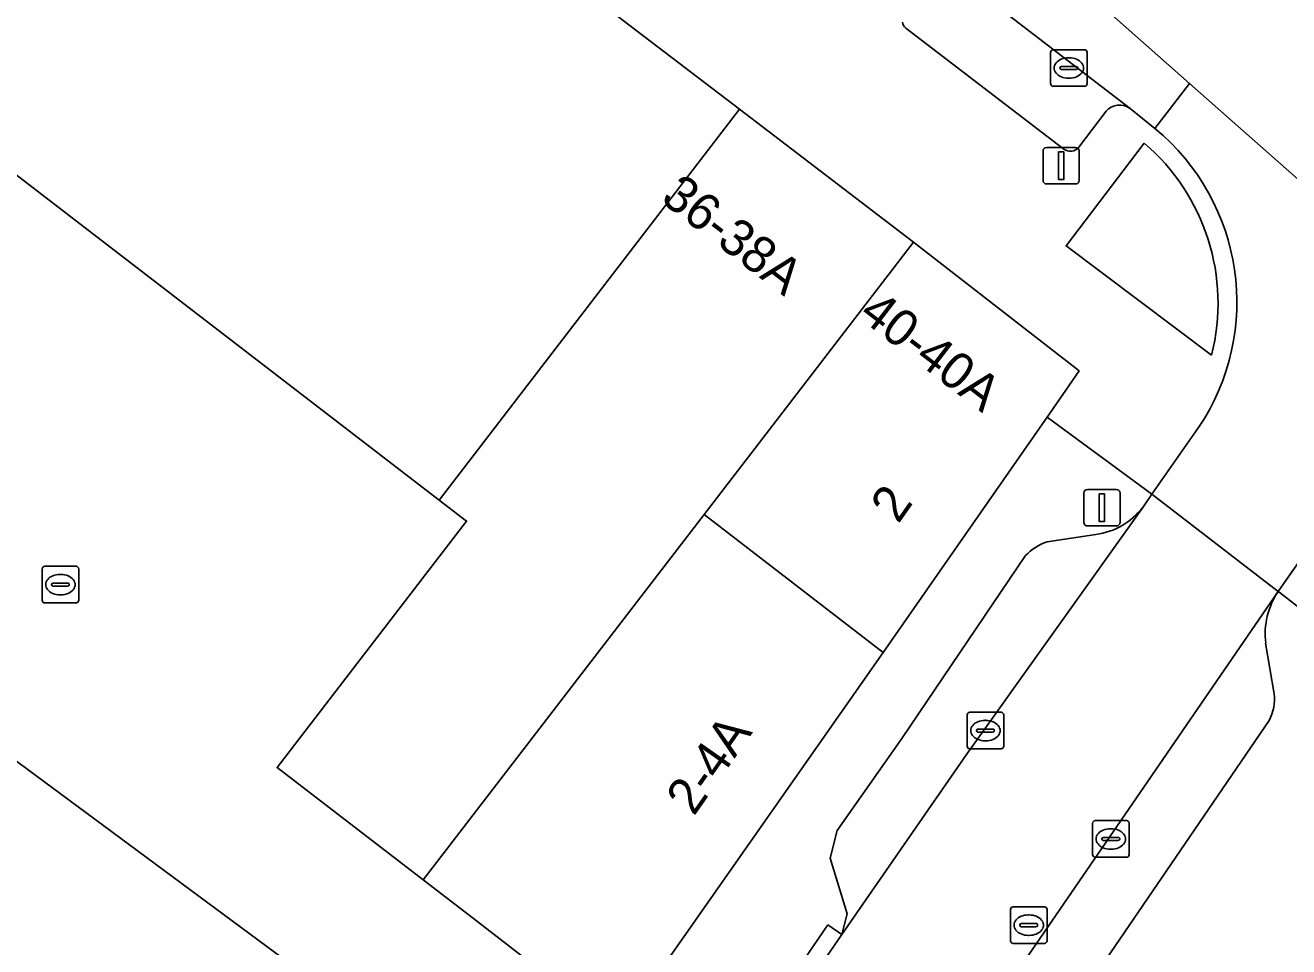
# Model space of a CAD drawing. Extents: x 161798 to 162385, y 382315 to 382833.
# Drawn here: x 161957.55 to 161992.07, y 382759.31 to 382784.49 of the extents above; entities that cross this region are included whole.
import ezdxf

# ---------------------------------------------------------------- set-up
doc = ezdxf.new("R2010")
doc.units = 0
for name, color, linetype in [('IMGEO_Groenvoorziening', 7, 'Continuous'), ('IMGEO_Kolk', 7, 'Continuous'), ('IMGEO_Lichtmast', 7, 'Continuous'), ('IMGEO_Pand', 7, 'Continuous'), ('IMGEO_Pand_nummerreeks', 7, 'Continuous'), ('IMGEO_Parkeervlak_open', 7, 'Continuous'), ('IMGEO_Rijbaan_lokaal_gesloten', 7, 'Continuous'), ('IMGEO_Rijbaan_lokaal_open', 7, 'Continuous'), ('IMGEO_Rioolput', 7, 'Continuous'), ('IMGEO_Voetpad_open', 7, 'Continuous')]:
    doc.layers.add(name, color=color, linetype=linetype)

msp = doc.modelspace()

# ---------------------------------------------------------------- linework, layer by layer
at = {"layer": 'IMGEO_Groenvoorziening'}
msp.add_lwpolyline([(161988.128, 382781.269), (161985.99, 382778.458), (161989.966, 382775.475)], dxfattribs=at)
msp.add_arc((161984.376, 382776.89), 5.766, 345.7922, 49.4085, dxfattribs=at)
at = {"layer": 'IMGEO_Kolk'}
for p, q in [((161985.64, 382783.82), (161986.492, 382783.82)), ((161985.565, 382782.894), (161985.565, 382783.746)), ((161986.053, 382783.6), (161986.078, 382783.6)), ((161986.566, 382783.746), (161986.566, 382782.894)), ((161985.824, 382783.314), (161985.824, 382783.326)), ((161986.262, 382783.277), (161985.864, 382783.277)), ((161985.867, 382783.363), (161986.265, 382783.363)), ((161986.308, 382783.326), (161986.308, 382783.314)), ((161986.492, 382782.82), (161985.64, 382782.82)), ((161986.076, 382783.04), (161986.051, 382783.04)), ((161958.012, 382768.778), (161958.012, 382769.63)), ((161958.087, 382769.704), (161958.939, 382769.704)), ((161959.013, 382769.63), (161959.013, 382768.778)), ((161958.5, 382769.484), (161958.525, 382769.484)), ((161958.271, 382769.198), (161958.271, 382769.21)), ((161958.709, 382769.161), (161958.311, 382769.161)), ((161958.314, 382769.247), (161958.712, 382769.247)), ((161958.755, 382769.21), (161958.755, 382769.198)), ((161958.939, 382768.704), (161958.087, 382768.704)), ((161958.523, 382768.924), (161958.498, 382768.924)), ((161983.286, 382764.789), (161983.286, 382765.641)), ((161983.361, 382765.715), (161984.213, 382765.715)), ((161983.774, 382765.495), (161983.799, 382765.495)), ((161984.287, 382765.641), (161984.287, 382764.789)), ((161983.545, 382765.209), (161983.545, 382765.221)), ((161983.983, 382765.172), (161983.585, 382765.172)), ((161983.588, 382765.258), (161983.986, 382765.258)), ((161984.029, 382765.221), (161984.029, 382765.209)), ((161983.797, 382764.935), (161983.772, 382764.935)), ((161984.213, 382764.715), (161983.361, 382764.715)), ((161986.787, 382762.754), (161987.639, 382762.754)), ((161986.712, 382761.828), (161986.712, 382762.68)), ((161987.2, 382762.534), (161987.225, 382762.534)), ((161987.713, 382762.68), (161987.713, 382761.828)), ((161986.971, 382762.248), (161986.971, 382762.26)), ((161987.409, 382762.211), (161987.011, 382762.211)), ((161987.014, 382762.297), (161987.412, 382762.297)), ((161987.455, 382762.26), (161987.455, 382762.248)), ((161987.639, 382761.754), (161986.787, 382761.754)), ((161987.223, 382761.974), (161987.198, 382761.974))]:
    msp.add_line(p, q, dxfattribs=at)
for points in [[(161985.64, 382783.82), (161986.492, 382783.82)], [(161985.565, 382782.894), (161985.565, 382783.746)], [(161986.566, 382783.746), (161986.566, 382782.894)], [(161986.492, 382782.82), (161985.64, 382782.82)], [(161958.012, 382768.778), (161958.012, 382769.63)], [(161958.087, 382769.704), (161958.939, 382769.704)], [(161959.013, 382769.63), (161959.013, 382768.778)], [(161958.939, 382768.704), (161958.087, 382768.704)], [(161983.286, 382764.789), (161983.286, 382765.641)], [(161983.361, 382765.715), (161984.213, 382765.715)], [(161984.287, 382765.641), (161984.287, 382764.789)], [(161984.213, 382764.715), (161983.361, 382764.715)], [(161986.787, 382762.754), (161987.639, 382762.754)], [(161986.712, 382761.828), (161986.712, 382762.68)], [(161987.713, 382762.68), (161987.713, 382761.828)], [(161987.639, 382761.754), (161986.787, 382761.754)]]:
    msp.add_lwpolyline(points, dxfattribs=at)
for centre, radius, start, end in [((161985.642, 382783.744), 0.0765, 91.552, 178.448), ((161985.642, 382783.744), 0.0765, 91.552, 178.448), ((161986.49, 382783.744), 0.0765, 1.552, 88.448), ((161986.49, 382783.744), 0.0765, 1.552, 88.448), ((161985.864, 382783.323), 0.0403, 85.8775, 175.7526), ((161985.861, 382783.313), 0.0366, 178.938, 274.7102), ((161986.265, 382783.32), 0.043, 264.8664, 352.4533), ((161986.269, 382783.325), 0.0386, 1.7309, 96.639), ((161985.642, 382782.896), 0.0765, 181.552, 268.448), ((161985.642, 382782.896), 0.0765, 181.552, 268.448), ((161986.49, 382782.896), 0.0765, 271.552, 358.448), ((161986.49, 382782.896), 0.0765, 271.552, 358.448), ((161958.089, 382769.628), 0.0765, 91.552, 178.448), ((161958.089, 382769.628), 0.0765, 91.552, 178.448), ((161958.937, 382769.628), 0.0765, 1.552, 88.448), ((161958.937, 382769.628), 0.0765, 1.552, 88.448), ((161958.311, 382769.207), 0.0403, 85.8775, 175.7526), ((161958.308, 382769.197), 0.0366, 178.938, 274.7102), ((161958.712, 382769.204), 0.043, 264.8664, 352.4533), ((161958.716, 382769.209), 0.0386, 1.7309, 96.639), ((161958.089, 382768.78), 0.0765, 181.552, 268.448), ((161958.089, 382768.78), 0.0765, 181.552, 268.448), ((161958.937, 382768.78), 0.0765, 271.552, 358.448), ((161958.937, 382768.78), 0.0765, 271.552, 358.448), ((161983.363, 382765.639), 0.0765, 91.552, 178.448), ((161983.363, 382765.639), 0.0765, 91.552, 178.448), ((161984.211, 382765.639), 0.0765, 1.552, 88.448), ((161984.211, 382765.639), 0.0765, 1.552, 88.448), ((161983.585, 382765.218), 0.0403, 85.8775, 175.7526), ((161983.582, 382765.208), 0.0366, 178.938, 274.7102), ((161983.986, 382765.215), 0.043, 264.8664, 352.4533), ((161983.99, 382765.22), 0.0386, 1.7309, 96.639), ((161983.363, 382764.791), 0.0765, 181.552, 268.448), ((161983.363, 382764.791), 0.0765, 181.552, 268.448), ((161984.211, 382764.791), 0.0765, 271.552, 358.448), ((161984.211, 382764.791), 0.0765, 271.552, 358.448), ((161986.789, 382762.678), 0.0765, 91.552, 178.448), ((161986.789, 382762.678), 0.0765, 91.552, 178.448), ((161987.637, 382762.678), 0.0765, 1.552, 88.448), ((161987.637, 382762.678), 0.0765, 1.552, 88.448), ((161987.011, 382762.257), 0.0403, 85.8775, 175.7526), ((161987.008, 382762.247), 0.0366, 178.938, 274.7102), ((161987.412, 382762.254), 0.043, 264.8664, 352.4533), ((161987.416, 382762.259), 0.0386, 1.7309, 96.639), ((161986.789, 382761.83), 0.0765, 181.552, 268.448), ((161986.789, 382761.83), 0.0765, 181.552, 268.448), ((161987.637, 382761.83), 0.0765, 271.552, 358.448), ((161987.637, 382761.83), 0.0765, 271.552, 358.448)]:
    msp.add_arc(centre, radius, start, end, dxfattribs=at)
for centre, major_axis, ratio, start_param, end_param in [((161986.052, 382783.32), (-0.387, 0.002), 0.722429, 4.712389, 7.853982), ((161986.077, 382783.32), (-0.39, 0.002), 0.717154, 1.570796, 4.712389), ((161958.499, 382769.204), (-0.387, 0.002), 0.722429, 4.712389, 7.853982), ((161958.524, 382769.204), (-0.39, 0.002), 0.717154, 1.570796, 4.712389), ((161983.773, 382765.215), (-0.387, 0.002), 0.722429, 4.712389, 7.853982), ((161983.798, 382765.215), (-0.39, 0.002), 0.717154, 1.570796, 4.712389), ((161987.199, 382762.254), (-0.387, 0.002), 0.722429, 4.712389, 7.853982), ((161987.224, 382762.254), (-0.39, 0.002), 0.717154, 1.570796, 4.712389)]:
    msp.add_ellipse(centre, major_axis=major_axis, ratio=ratio, start_param=start_param, end_param=end_param, dxfattribs=at)
at = {"layer": 'IMGEO_Lichtmast'}
for p, q in [((161985.36, 382780.251), (161985.36, 382781.051)), ((161985.36, 382781.051), (161985.36, 382780.251)), ((161985.46, 382781.151), (161986.25, 382781.151)), ((161986.25, 382781.151), (161985.46, 382781.151)), ((161986.35, 382781.051), (161986.35, 382780.251)), ((161986.35, 382780.251), (161986.35, 382781.051)), ((161986.25, 382780.151), (161985.46, 382780.151)), ((161985.46, 382780.151), (161986.25, 382780.151)), ((161986.474, 382770.906), (161986.474, 382771.706)), ((161986.474, 382771.706), (161986.474, 382770.906)), ((161986.574, 382771.806), (161987.364, 382771.806)), ((161987.364, 382771.806), (161986.574, 382771.806)), ((161987.464, 382771.706), (161987.464, 382770.906)), ((161987.464, 382770.906), (161987.464, 382771.706)), ((161987.364, 382770.806), (161986.574, 382770.806)), ((161986.574, 382770.806), (161987.364, 382770.806))]:
    msp.add_line(p, q, dxfattribs=at)
for points in [[(161985.78, 382781.026), (161985.93, 382781.026), (161985.93, 382780.276), (161985.78, 382780.276), (161985.78, 382781.026)], [(161986.894, 382771.681), (161987.044, 382771.681), (161987.044, 382770.931), (161986.894, 382770.931), (161986.894, 382771.681)]]:
    msp.add_lwpolyline(points, dxfattribs=at)
for centre, start, end in [((161985.46, 382781.051), 90, 180), ((161985.46, 382781.051), 90, 180), ((161986.25, 382781.051), 0, 90), ((161986.25, 382781.051), 360, 90), ((161985.46, 382780.251), 180, 270), ((161985.46, 382780.251), 180, 270), ((161986.25, 382780.251), 270, 0), ((161986.25, 382780.251), 270, 0), ((161986.574, 382771.706), 90, 180), ((161986.574, 382771.706), 90, 180), ((161987.364, 382771.706), 0, 90), ((161987.364, 382771.706), 360, 90), ((161986.574, 382770.906), 180, 270), ((161986.574, 382770.906), 180, 270), ((161987.364, 382770.906), 270, 0), ((161987.364, 382770.906), 270, 0)]:
    msp.add_arc(centre, 0.1, start, end, dxfattribs=at)
at = {"layer": 'IMGEO_Pand'}
for points in [[(161961.207, 382794.293), (161958.186, 382790.352), (161955.695, 382792.246), (161950.654, 382785.52), (161968.864, 382771.513), (161977.065, 382782.193)], [(161981.82, 382778.558), (161977.065, 382782.193), (161968.864, 382771.513), (161969.61, 382770.941), (161964.431, 382764.206), (161968.421, 382761.136), (161976.102, 382771.121)], [(161985.47, 382773.783), (161985.533, 382773.874), (161986.343, 382775.044), (161981.82, 382778.558), (161976.102, 382771.121), (161980.996, 382767.347)], [(161980.996, 382767.347), (161976.102, 382771.121), (161968.421, 382761.136), (161969.677, 382760.169), (161973.752, 382757.022)]]:
    msp.add_lwpolyline(points, close=True, dxfattribs=at)
msp.add_lwpolyline([(161955.042, 382743.822), (161958.233, 382748.137), (161960.189, 382746.69), (161960.524, 382747.144), (161958.536, 382748.615), (161959.56, 382750), (161961.787, 382753.011), (161963.782, 382751.536), (161964.103, 382751.97), (161962.085, 382753.462), (161965.327, 382757.846), (161967.374, 382756.333), (161967.663, 382756.723), (161954.083, 382766.765)], dxfattribs=at)
at = {"layer": 'IMGEO_Parkeervlak_open'}
for points in [[(161987.737, 382782.215), (161982.219, 382786.462)], [(161929.946, 382734.127), (161941.685, 382750), (161954.083, 382766.765), (161967.663, 382756.723), (161969.821, 382755.127), (161971.541, 382753.922), (161973.752, 382757.022), (161969.677, 382760.169), (161968.421, 382761.136), (161964.431, 382764.206), (161969.61, 382770.941), (161968.864, 382771.513), (161950.654, 382785.52), (161946.102, 382779.602), (161945.706, 382772.813), (161945.633, 382772.713), (161923.425, 382739.892), (161911.109, 382723.212), (161905.87, 382718.099), (161905.781, 382717.991)], [(161981.61, 382784.406), (161985.932, 382781.106)], [(161986.334, 382781.158), (161987.082, 382782.14)], [(161984.882, 382769.995), (161981.502, 382765.002), (161979.734, 382762.486), (161979.541, 382761.728), (161980.007, 382760.209), (161979.867, 382759.641), (161983.272, 382764.558), (161988.086, 382771.315)], [(161986.806, 382770.572), (161985.471, 382770.375)], [(161991.783, 382769.02), (161982.788, 382755.905), (161978.946, 382750.365)], [(161991.678, 382766.223), (161991.443, 382767.601)], [(161980.179, 382751.181), (161981.574, 382751.502), (161982.208, 382751.95), (161984.273, 382754.939), (161986.435, 382758.019), (161991.536, 382765.487)]]:
    msp.add_lwpolyline(points, dxfattribs=at)
for centre, radius, start, end in [((161981.829, 382784.638), 0.319, 191.4395, 226.7273), ((161987.451, 382781.817), 0.49, 54.277, 138.7872), ((161986.108, 382781.325), 0.281, 231.1813, 323.5596), ((161986.533, 382772.517), 1.964, 277.9957, 322.272), ((161985.943, 382768.998), 1.456, 108.8997, 136.7574), ((161993.56, 382767.844), 2.13, 146.499, 186.5523), ((161990.456, 382766.077), 1.231, 331.3522, 6.8075)]:
    msp.add_arc(centre, radius, start, end, dxfattribs=at)
at = {"layer": 'IMGEO_Rijbaan_lokaal_gesloten'}
msp.add_lwpolyline([(161951.28, 382808.889), (161952.743, 382807.885), (161957.652, 382804.49), (161963.263, 382800.55), (161964.723, 382799.511), (161973.915, 382792.787), (161979.949, 382788.264), (161982.219, 382786.462), (161987.737, 382782.215), (161988.419, 382781.669), (161989.366, 382782.899), (161984.797, 382786.939)], dxfattribs=at)
at = {"layer": 'IMGEO_Rijbaan_lokaal_open'}
for points in [[(161999.533, 382774.178), (161995.879, 382777.141), (161989.366, 382782.899), (161988.419, 382781.669)], [(161989.611, 382773.497), (161988.335, 382771.671), (161991.783, 382769.02), (161994.37, 382772.717)], [(161953.014, 382713.254), (161953.841, 382714.33), (161954.011, 382714.515), (161954.232, 382714.711), (161974.497, 382744.072), (161975.012, 382744.815), (161978.57, 382749.833), (161978.687, 382750), (161978.946, 382750.365), (161982.788, 382755.905), (161991.783, 382769.02), (161988.335, 382771.671), (161988.086, 382771.315), (161983.272, 382764.558), (161979.867, 382759.641), (161975.168, 382752.813), (161974.155, 382751.509), (161950.871, 382717.792)]]:
    msp.add_lwpolyline(points, dxfattribs=at)
msp.add_arc((161984.503, 382776.925), 6.152, 326.1361, 50.4617, dxfattribs=at)
at = {"layer": 'IMGEO_Rioolput'}
for p, q in [((161984.47, 382759.472), (161984.47, 382760.324)), ((161984.545, 382760.398), (161985.397, 382760.398)), ((161985.471, 382760.324), (161985.471, 382759.472)), ((161984.958, 382760.178), (161984.983, 382760.178)), ((161984.729, 382759.892), (161984.729, 382759.904)), ((161985.167, 382759.855), (161984.769, 382759.855)), ((161984.772, 382759.941), (161985.17, 382759.941)), ((161984.981, 382759.618), (161984.956, 382759.618)), ((161985.213, 382759.904), (161985.213, 382759.892)), ((161985.397, 382759.398), (161984.545, 382759.398))]:
    msp.add_line(p, q, dxfattribs=at)
for points in [[(161984.47, 382759.472), (161984.47, 382760.324)], [(161984.545, 382760.398), (161985.397, 382760.398)], [(161985.471, 382760.324), (161985.471, 382759.472)], [(161985.397, 382759.398), (161984.545, 382759.398)]]:
    msp.add_lwpolyline(points, dxfattribs=at)
for centre, radius, start, end in [((161984.547, 382760.322), 0.0765, 91.552, 178.448), ((161984.547, 382760.322), 0.0765, 91.552, 178.448), ((161985.395, 382760.322), 0.0765, 1.552, 88.448), ((161985.395, 382760.322), 0.0765, 1.552, 88.448), ((161984.769, 382759.901), 0.0403, 85.8775, 175.7526), ((161984.766, 382759.891), 0.0366, 178.938, 274.7102), ((161985.17, 382759.898), 0.043, 264.8664, 352.4533), ((161985.174, 382759.903), 0.0386, 1.7309, 96.639), ((161984.547, 382759.474), 0.0765, 181.552, 268.448), ((161984.547, 382759.474), 0.0765, 181.552, 268.448), ((161985.395, 382759.474), 0.0765, 271.552, 358.448), ((161985.395, 382759.474), 0.0765, 271.552, 358.448)]:
    msp.add_arc(centre, radius, start, end, dxfattribs=at)
for centre, major_axis, ratio, start_param, end_param in [((161984.957, 382759.898), (-0.387, 0.002), 0.722429, 4.712389, 7.853982), ((161984.982, 382759.898), (-0.39, 0.002), 0.717154, 1.570796, 4.712389)]:
    msp.add_ellipse(centre, major_axis=major_axis, ratio=ratio, start_param=start_param, end_param=end_param, dxfattribs=at)
at = {"layer": 'IMGEO_Voetpad_open'}
for points in [[(161957.244, 382796.796), (161961.207, 382794.293), (161977.065, 382782.193), (161981.82, 382778.558), (161986.343, 382775.044), (161985.533, 382773.874), (161985.47, 382773.783), (161988.335, 382771.671), (161989.611, 382773.497)], [(161985.932, 382781.106), (161981.61, 382784.406)], [(161987.082, 382782.14), (161986.334, 382781.158)], [(161988.419, 382781.669), (161987.737, 382782.215)], [(161989.966, 382775.475), (161985.99, 382778.458), (161988.128, 382781.269)], [(161988.086, 382771.315), (161988.335, 382771.671), (161985.47, 382773.783), (161980.996, 382767.347), (161973.752, 382757.022), (161971.541, 382753.922), (161969.821, 382755.127), (161966.31, 382750), (161945.78, 382720.02), (161941.286, 382714.73), (161942.474, 382713.523), (161925.083, 382696.984), (161927.394, 382694.49), (161927.839, 382694.207), (161928.944, 382695.23)], [(161994.37, 382772.717), (161991.783, 382769.02), (161991.848, 382768.97), (161997.519, 382764.558), (161998.609, 382765.767), (162000, 382764.491), (162003.821, 382761.079), (162009.776, 382755.729), (162015.335, 382750.798), (162016.083, 382750.117), (162017.324, 382748.986), (162022.858, 382743.945), (162027.754, 382739.543), (162038.012, 382730.344), (162043.809, 382725.145), (162045.819, 382722.219)], [(161985.471, 382770.375), (161986.806, 382770.572)], [(161955.922, 382732.912), (161958.647, 382733.757), (161957.979, 382735.907), (161960.71, 382736.757), (161960.061, 382738.905), (161962.784, 382739.751), (161962.14, 382741.911), (161964.866, 382742.715), (161964.207, 382744.9), (161966.947, 382745.726), (161966.314, 382747.929), (161969.029, 382748.71), (161968.649, 382750), (161968.392, 382750.903), (161975.168, 382752.813), (161974.785, 382753.021), (161979.484, 382759.903), (161979.867, 382759.641), (161980.007, 382760.209), (161979.541, 382761.728), (161979.734, 382762.486), (161981.502, 382765.002), (161984.882, 382769.995)], [(161953.212, 382706.879), (161955.826, 382710.123), (161981.747, 382747.198), (161984.249, 382750), (161997.519, 382764.558), (161991.848, 382768.97), (161991.783, 382769.02)], [(161991.443, 382767.601), (161991.678, 382766.223)], [(161991.536, 382765.487), (161986.435, 382758.019), (161986.82, 382757.755), (161984.633, 382754.664), (161984.273, 382754.939), (161982.208, 382751.95), (161981.574, 382751.502), (161980.179, 382751.181)]]:
    msp.add_lwpolyline(points, dxfattribs=at)
msp.add_lwpolyline([(161979.867, 382759.641), (161979.484, 382759.903), (161974.785, 382753.021), (161975.168, 382752.813)], close=True, dxfattribs=at)
for centre, radius, start, end in [((161981.829, 382784.638), 0.319, 191.4395, 226.7273), ((161987.451, 382781.817), 0.49, 54.277, 138.7872), ((161984.503, 382776.925), 6.152, 326.1361, 50.4617), ((161986.108, 382781.325), 0.281, 231.1813, 323.5596), ((161984.376, 382776.89), 5.766, 345.7922, 49.4085), ((161986.533, 382772.517), 1.964, 277.9957, 322.272), ((161985.943, 382768.998), 1.456, 108.8997, 136.7574), ((161993.56, 382767.844), 2.13, 146.499, 186.5523), ((161990.456, 382766.077), 1.231, 331.3522, 6.8075)]:
    msp.add_arc(centre, radius, start, end, dxfattribs=at)

# ---------------------------------------------------------------- texts
at = {"layer": 'IMGEO_Pand_nummerreeks'}
for s, rotation, p in [('36-38A', 322.4312, (161974.877, 382779.693)), ('40-40A', 322.4312, (161980.289, 382776.512)), ('2', 55.0326, (161981.405, 382770.843)), ('2-4A', 55.0383, (161975.82, 382762.856))]:
    msp.add_text(s, height=1, rotation=rotation, dxfattribs=at).set_placement(p)

doc.saveas('drawing.dxf')
